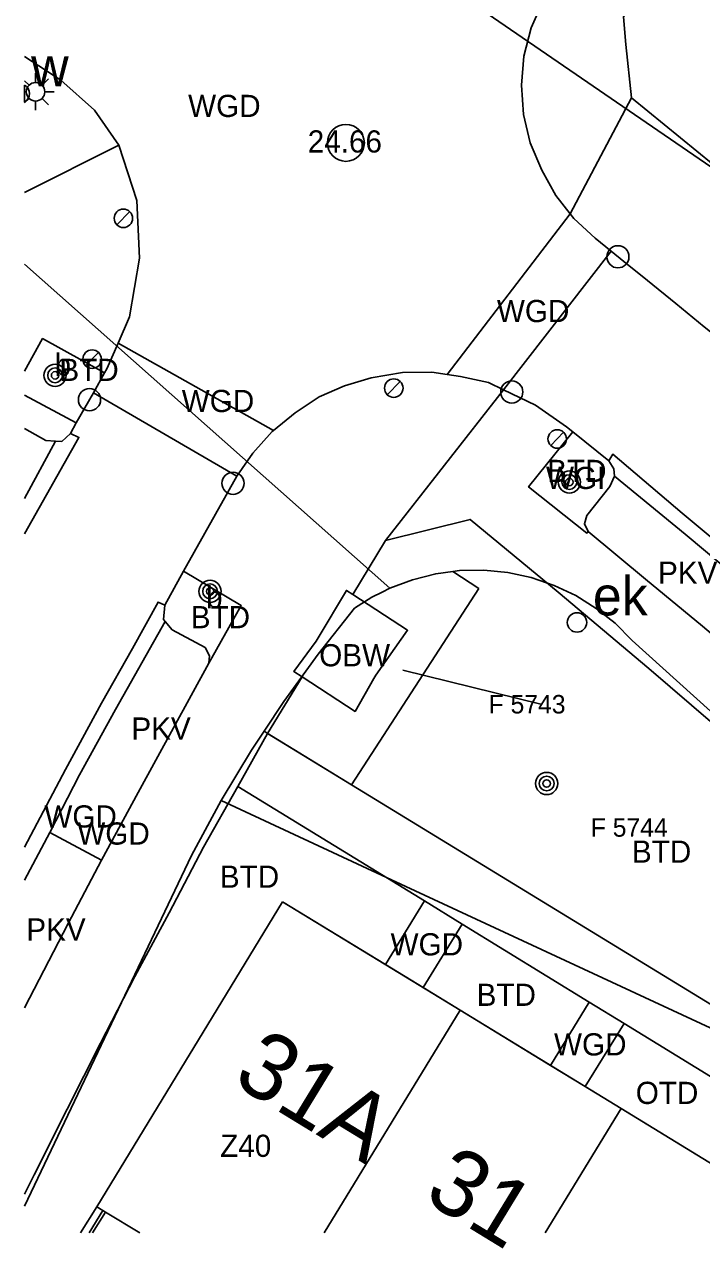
# Model space of a CAD drawing. Extents: x 198240 to 198429, y 356553 to 356721.
# Drawn here: x 198239.79 to 198258.1, y 356553.28 to 356586.38 of the extents above; entities that cross this region are included whole.
import ezdxf

# ---------------------------------------------------------------- set-up
doc = ezdxf.new("R2010")
doc.units = 0
for name, color, linetype in [('Afsluitpaal', 7, 'Continuous'), ('begroeid terreindeel kenmerkpunt', 7, 'Continuous'), ('bijpijling', 7, 'Continuous'), ('BOOM', 7, 'Continuous'), ('Elektrakast', 7, 'Continuous'), ('Grens beheer openbare ruimte', 7, 'Continuous'), ('Grens beheer openbare ruimte wegbeheer', 7, 'Continuous'), ('grens individueel parkeervak', 7, 'Continuous'), ('Grens maaiveld', 7, 'Continuous'), ('hoofdgebouw', 7, 'Continuous'), ('Hoogtepunt', 7, 'Continuous'), ('huisnummerreeks BGT', 7, 'Continuous'), ('identificerend kenmerkpunt pand', 7, 'Continuous'), ('identificerend kenmerkpunt parkeervak', 7, 'Continuous'), ('Inspectieput_rioolput', 7, 'Continuous'), ('kant verharding', 7, 'Continuous'), ('kolk', 7, 'Continuous'), ('LICHTMAST', 7, 'Continuous'), ('muur breder dan 30cm', 7, 'Continuous'), ('onbegroeid terreindeel kenmerkpunt', 7, 'Continuous'), ('overig bouwwerk kenmerkpunt', 7, 'Continuous'), ('overig opstal', 7, 'Continuous'), ('Perceelnummer', 7, 'Continuous'), ('perceelsgrens_definitief', 7, 'Continuous'), ('scheidingmuur boven maaiveld', 7, 'Continuous'), ('schutting geen IMGeo', 7, 'Continuous'), ('tussenmuur', 7, 'Continuous'), ('vlakafsluiter', 7, 'Continuous'), ('waterleidingput', 7, 'Continuous'), ('wegdeel kenmerkpunt', 7, 'Continuous'), ('weginrichtingselement', 7, 'Continuous'), ('weginrichtingselement lijn', 7, 'Continuous')]:
    doc.layers.add(name, color=color, linetype=linetype)

msp = doc.modelspace()

# ---------------------------------------------------------------- linework, layer by layer
at = {"layer": 'Afsluitpaal'}
for p, q in [((198242.636, 356581.32), (198242.286, 356580.963)), ((198241.791, 356577.511), (198241.441, 356577.154)), ((198249.95, 356576.728), (198249.6, 356576.371)), ((198254.371, 356575.354), (198254.021, 356574.997))]:
    msp.add_line(p, q, dxfattribs=at)
for centre in [(198242.463, 356581.14), (198241.618, 356577.331), (198249.777, 356576.548), (198254.198, 356575.174)]:
    msp.add_circle(centre, 0.25, dxfattribs=at)
at = {"layer": 'bijpijling'}
msp.add_lwpolyline([(198250.02, 356568.921), (198253.758, 356568)], dxfattribs=at)
at = {"layer": 'BOOM'}
for centre, radius in [((198240.615, 356576.894), 0.3), ((198240.615, 356576.894), 0.2), ((198240.615, 356576.894), 0.1), ((198254.526, 356574.008), 0.3), ((198254.526, 356574.008), 0.2), ((198254.526, 356574.008), 0.1), ((198244.808, 356571.052), 0.3), ((198244.808, 356571.052), 0.2), ((198244.808, 356571.052), 0.1), ((198253.913, 356565.857), 0.3), ((198253.913, 356565.857), 0.2), ((198253.913, 356565.857), 0.1)]:
    msp.add_circle(centre, radius, dxfattribs=at)
at = {"layer": 'Elektrakast'}
msp.add_circle((198254.733, 356570.212), 0.263, dxfattribs=at)
msp.add_circle((198254.733, 356570.212), 0.263, dxfattribs=at)
at = {"layer": 'Grens beheer openbare ruimte'}
for p, q in [((198249.557, 356572.425), (198252.744, 356576.504)), ((198245.558, 356565.779), (198246.362, 356567.205))]:
    msp.add_line(p, q, dxfattribs=at)
at = {"layer": 'Grens beheer openbare ruimte wegbeheer'}
msp.add_line((198242.319, 356577.767), (198246.52, 356575.403), dxfattribs=at)
at = {"layer": 'grens individueel parkeervak'}
msp.add_line((198240.471, 356564.536), (198241.874, 356563.779), dxfattribs=at)
at = {"layer": 'Grens maaiveld'}
for p, q in [((198254.551, 356581.262), (198251.221, 356576.917)), ((198252.744, 356576.504), (198255.653, 356580.25)), ((198241.65, 356576.424), (198245.534, 356574.17)), ((198245.558, 356565.779), (198250.608, 356562.68)), ((198246.769, 356562.661), (198249.553, 356560.96)), ((198249.553, 356560.96), (198250.608, 356562.68)), ((198251.627, 356562.055), (198250.608, 356562.68)), ((198250.573, 356560.337), (198251.627, 356562.055)), ((198255.066, 356559.945), (198251.627, 356562.055)), ((198250.573, 356560.337), (198249.553, 356560.96)), ((198250.573, 356560.337), (198251.576, 356559.724)), ((198254.016, 356558.234), (198255.066, 356559.945)), ((198255.066, 356559.945), (198256.006, 356559.368)), ((198251.576, 356559.724), (198254.016, 356558.234)), ((198254.957, 356557.659), (198256.006, 356559.368)), ((198256.006, 356559.368), (198259.345, 356557.319)), ((198254.016, 356558.234), (198254.957, 356557.659)), ((198255.928, 356557.066), (198254.957, 356557.659)), ((198258.3, 356555.616), (198255.928, 356557.066))]:
    msp.add_line(p, q, dxfattribs=at)
for points in [[(198239.787, 356572.605), (198241.259, 356575.215), (198241.033, 356575.321)], [(198255.592, 356574.585), (198255.699, 356574.762), (198257.573, 356573.165), (198259.411, 356571.648), (198260.875, 356570.386), (198262.5, 356568.968), (198264.152, 356567.503), (198265.781, 356566.067), (198267.427, 356564.565), (198269.308, 356562.845), (198271.085, 356561.21), (198272.778, 356559.643), (198274.563, 356557.947), (198276.281, 356556.309), (198277.654, 356554.959), (198278.872, 356553.781), (198278.805, 356553.702)], [(198239.787, 356564.132), (198240.9, 356566.232), (198241.873, 356568.027), (198242.71, 356569.511), (198243.402, 356570.763), (198243.582, 356570.681)]]:
    msp.add_lwpolyline(points, dxfattribs=at)
at = {"layer": 'hoofdgebouw'}
for p, q in [((198241.747, 356554.408), (198241.909, 356554.309)), ((198241.909, 356554.309), (198241.977, 356554.268)), ((198241.977, 356554.268), (198242.907, 356553.702))]:
    msp.add_line(p, q, dxfattribs=at)
at = {"layer": 'Inspectieput_rioolput'}
msp.add_circle((198248.481, 356583.18), 0.5, dxfattribs=at)
at = {"layer": 'kant verharding'}
for p, q in [((198256.055, 356585.841), (198256.204, 356584.398)), ((198256.204, 356584.398), (198258.856, 356582.232)), ((198241.65, 356576.424), (198241.954, 356576.965)), ((198241.19, 356575.606), (198241.65, 356576.424)), ((198241.033, 356575.321), (198241.19, 356575.606)), ((198255.592, 356574.585), (198254.621, 356575.367)), ((198240.624, 356575.114), (198239.787, 356573.563)), ((198244.093, 356571.595), (198245.534, 356574.17)), ((198249.557, 356572.425), (198248.665, 356570.967)), ((198243.582, 356570.681), (198244.093, 356571.595)), ((198247.299, 356568.737), (198246.362, 356567.205)), ((198246.362, 356567.205), (198268.466, 356553.702))]:
    msp.add_line(p, q, dxfattribs=at)
for points in [[(198256.055, 356585.841), (198255.989, 356586.59), (198257.636, 356589.092), (198257.545, 356589.159), (198257.648, 356589.317)], [(198254.653, 356588.377), (198254.218, 356587.696), (198253.817, 356587.017), (198253.496, 356586.295), (198253.293, 356585.524), (198253.233, 356584.742), (198253.288, 356583.945), (198253.466, 356583.177), (198253.779, 356582.443), (198254.159, 356581.761), (198254.551, 356581.262)], [(198239.787, 356585.517), (198240.771, 356584.875), (198241.681, 356584.067), (198242.343, 356583.12)], [(198242.343, 356583.12), (198242.826, 356581.623), (198242.899, 356580.059), (198242.63, 356578.478), (198242.319, 356577.767)], [(198254.551, 356581.262), (198254.647, 356581.139), (198255.223, 356580.6), (198255.653, 356580.25)], [(198255.653, 356580.25), (198255.998, 356579.968), (198256.636, 356579.462), (198257.404, 356578.839), (198258.176, 356578.204), (198258.972, 356577.566), (198259.754, 356576.936), (198260.504, 356576.293), (198261.252, 356575.651), (198262.011, 356574.998)], [(198239.787, 356577.006), (198240.279, 356577.889), (198241.954, 356576.965)], [(198242.319, 356577.767), (198242.015, 356577.073), (198241.954, 356576.965)], [(198251.221, 356576.917), (198250.807, 356576.977), (198250.015, 356576.968), (198249.162, 356576.831), (198248.443, 356576.611), (198247.76, 356576.317), (198247.107, 356575.882), (198246.52, 356575.403)], [(198252.744, 356576.504), (198252.341, 356576.698), (198251.581, 356576.864), (198251.221, 356576.917)], [(198254.621, 356575.367), (198254.449, 356575.506), (198253.614, 356576.084), (198252.744, 356576.504)], [(198241.19, 356575.606), (198239.787, 356576.358)], [(198239.787, 356575.454), (198240.361, 356575.135), (198240.624, 356575.114)], [(198240.624, 356575.114), (198240.796, 356575.101), (198241.033, 356575.321)], [(198246.52, 356575.403), (198246.487, 356575.376), (198245.964, 356574.785), (198245.534, 356574.17)], [(198254.621, 356575.367), (198253.424, 356573.876), (198255.001, 356572.628), (198255.033, 356572.668)], [(198255.749, 356574.163), (198255.73, 356574.365), (198255.592, 356574.585)], [(198255.033, 356572.668), (198254.933, 356572.882), (198254.998, 356573.106), (198255.623, 356573.892), (198255.749, 356574.163)], [(198260.773, 356569.956), (198260.331, 356570.341), (198259.198, 356571.307), (198257.655, 356572.598), (198255.749, 356574.163)], [(198273.472, 356553.702), (198272.817, 356554.33), (198270.586, 356556.469), (198268.355, 356558.558), (198265.988, 356560.735), (198263.879, 356562.635), (198261.324, 356564.926), (198258.988, 356566.982), (198256.674, 356568.965), (198254.222, 356571.03), (198251.842, 356572.999), (198249.557, 356572.425)], [(198259.73, 356568.743), (198259.258, 356569.155), (198258.124, 356570.109), (198256.585, 356571.386), (198255.033, 356572.668)], [(198244.777, 356569.107), (198245.649, 356570.669), (198244.093, 356571.595)], [(198243.582, 356570.681), (198243.547, 356570.29), (198243.591, 356570.239)], [(198240.471, 356564.536), (198241.274, 356566.087), (198242.254, 356567.862), (198243.591, 356570.239)], [(198243.591, 356570.239), (198243.785, 356570.014), (198244.671, 356569.53), (198244.796, 356569.311), (198244.777, 356569.107)], [(198244.777, 356569.107), (198242.867, 356565.617), (198241.874, 356563.779)], [(198245.558, 356565.779), (198244.633, 356564.138), (198243.704, 356562.355), (198242.769, 356560.636), (198241.845, 356558.834), (198240.94, 356557.047), (198240.047, 356555.271), (198239.787, 356554.751)], [(198239.787, 356563.246), (198240.471, 356564.536)], [(198241.874, 356563.779), (198240.973, 356562.067), (198239.787, 356559.786)]]:
    msp.add_lwpolyline(points, dxfattribs=at)
at = {"layer": 'kolk'}
for centre in [(198255.839, 356580.1), (198241.546, 356576.235), (198252.969, 356576.445), (198245.428, 356573.976)]:
    msp.add_circle(centre, 0.3, dxfattribs=at)
at = {"layer": 'LICHTMAST'}
for p, q in [((198240.087, 356584.811), (198240.087, 356585.061)), ((198239.91, 356584.738), (198239.787, 356584.861)), ((198240.264, 356584.738), (198240.441, 356584.915)), ((198239.787, 356584.561), (198239.837, 356584.561)), ((198239.787, 356584.261), (198239.91, 356584.384)), ((198240.441, 356584.207), (198240.264, 356584.384)), ((198240.337, 356584.561), (198240.587, 356584.561)), ((198240.087, 356584.061), (198240.087, 356584.311))]:
    msp.add_line(p, q, dxfattribs=at)
msp.add_circle((198240.087, 356584.561), 0.25, dxfattribs=at)
at = {"layer": 'muur breder dan 30cm'}
for points in [[(198241.747, 356554.408), (198241.306, 356553.702)], [(198241.536, 356553.702), (198241.909, 356554.309)]]:
    msp.add_lwpolyline(points, dxfattribs=at)
at = {"layer": 'overig opstal'}
for points in [[(198247.299, 356568.737), (198247.074, 356568.883), (198247.679, 356569.709), (198247.736, 356569.796), (198248.496, 356571.077), (198248.665, 356570.967)], [(198248.665, 356570.967), (198250.149, 356569.999), (198249.288, 356568.783), (198249.238, 356568.7), (198248.73, 356567.808), (198247.299, 356568.737)]]:
    msp.add_lwpolyline(points, dxfattribs=at)
at = {"layer": 'perceelsgrens_definitief'}
for points in [[(198243.211, 356592.912), (198259.64, 356581.648)], [(198239.787, 356579.903), (198249.672, 356571.138)], [(198251.373, 356571.588), (198250.913, 356571.527), (198250.281, 356571.368), (198249.672, 356571.138)], [(198256.224, 356569.728), (198255.763, 356570.188), (198255.253, 356570.593), (198254.7, 356570.937), (198254.111, 356571.215), (198253.494, 356571.424), (198252.858, 356571.561), (198252.209, 356571.624), (198251.558, 356571.613), (198251.373, 356571.588)], [(198252.074, 356571.131), (198251.373, 356571.588)], [(198248.634, 356565.821), (198252.074, 356571.131)], [(198249.461, 356571.032), (198249.18, 356570.891), (198248.714, 356570.597)], [(198249.672, 356571.138), (198249.461, 356571.032)], [(198248.714, 356570.597), (198247.73, 356569.357), (198246.8, 356568.075), (198246.267, 356567.27)], [(198262.119, 356564.407), (198256.224, 356569.728)], [(198246.267, 356567.27), (198245.925, 356566.755), (198245.108, 356565.399)], [(198246.352, 356567.218), (198246.267, 356567.27)], [(198246.352, 356567.218), (198248.634, 356565.821)], [(198245.108, 356565.399), (198244.302, 356563.91)], [(198245.108, 356565.399), (198250.107, 356563.075)], [(198244.302, 356563.91), (198239.787, 356554.429)], [(198250.107, 356563.075), (198259.986, 356558.483), (198264.044, 356562.661)]]:
    msp.add_lwpolyline(points, dxfattribs=at)
at = {"layer": 'scheidingmuur boven maaiveld'}
for p, q in [((198251.576, 356559.724), (198246.769, 356562.661)), ((198251.576, 356559.724), (198255.928, 356557.066)), ((198260.28, 356554.407), (198255.928, 356557.066))]:
    msp.add_line(p, q, dxfattribs=at)
msp.add_lwpolyline([(198241.747, 356554.408), (198241.745, 356554.409), (198246.769, 356562.661)], dxfattribs=at)
at = {"layer": 'schutting geen IMGeo'}
msp.add_lwpolyline([(198241.977, 356554.268), (198241.63, 356553.702)], dxfattribs=at)
at = {"layer": 'tussenmuur'}
for p, q in [((198251.576, 356559.724), (198247.891, 356553.702)), ((198253.869, 356553.702), (198255.928, 356557.066))]:
    msp.add_line(p, q, dxfattribs=at)
at = {"layer": 'vlakafsluiter'}
for p, q in [((198254.551, 356581.262), (198256.204, 356584.398)), ((198239.787, 356581.841), (198242.343, 356583.12))]:
    msp.add_line(p, q, dxfattribs=at)
at = {"layer": 'waterleidingput'}
msp.add_line((198239.787, 356584.743), (198239.787, 356584.281), dxfattribs=at)
msp.add_line((198239.787, 356584.743), (198239.787, 356584.281), dxfattribs=at)
msp.add_arc((198239.663, 356584.512), 0.263, 298.2918, 61.7082, dxfattribs=at)
msp.add_arc((198239.663, 356584.512), 0.263, 298.2918, 61.7082, dxfattribs=at)
at = {"layer": 'weginrichtingselement lijn'}
for points in [[(198239.787, 356572.605), (198241.259, 356575.215), (198241.033, 356575.321)], [(198239.787, 356564.132), (198240.9, 356566.232), (198241.873, 356568.027), (198242.71, 356569.511), (198243.402, 356570.763), (198243.582, 356570.681)]]:
    msp.add_lwpolyline(points, dxfattribs=at)

# ---------------------------------------------------------------- texts
at = {"layer": 'begroeid terreindeel kenmerkpunt'}
for p in [(198240.732, 356576.743), (198253.927, 356574.01), (198244.285, 356570.055), (198256.219, 356563.715), (198245.072, 356563.037), (198252.018, 356559.843)]:
    msp.add_text('BTD', height=0.6, dxfattribs=at).set_placement(p)
at = {"layer": 'Elektrakast'}
msp.add_text('ek', height=1.05, dxfattribs=at).set_placement((198255.162, 356570.403))
at = {"layer": 'Hoogtepunt'}
msp.add_text('24.66', height=0.6, dxfattribs=at).set_placement((198247.449, 356582.919))
msp.add_text('24.66', height=0.6, dxfattribs=at).set_placement((198247.449, 356582.919))
at = {"layer": 'huisnummerreeks BGT'}
for s, p in [('31A', (198245.371, 356557.772)), ('31', (198250.539, 356554.615))]:
    msp.add_text(s, height=1.8, rotation=328.6, dxfattribs=at).set_placement(p)
at = {"layer": 'identificerend kenmerkpunt pand'}
msp.add_text('Z40', height=0.6, dxfattribs=at).set_placement((198245.081, 356555.76))
at = {"layer": 'identificerend kenmerkpunt parkeervak'}
for p in [(198256.925, 356571.257), (198242.679, 356567.042), (198239.837, 356561.609)]:
    msp.add_text('PKV', height=0.6, dxfattribs=at).set_placement(p)
at = {"layer": 'onbegroeid terreindeel kenmerkpunt'}
msp.add_text('OTD', height=0.6, dxfattribs=at).set_placement((198256.322, 356557.191))
at = {"layer": 'overig bouwwerk kenmerkpunt'}
msp.add_text('OBW', height=0.6, dxfattribs=at).set_placement((198247.76, 356569.025))
at = {"layer": 'Perceelnummer'}
for s, p in [('F 5743', (198252.341, 356567.75)), ('F 5744', (198255.105, 356564.418))]:
    msp.add_text(s, height=0.5, dxfattribs=at).set_placement(p)
at = {"layer": 'waterleidingput'}
msp.add_text('w', height=1.05, dxfattribs=at).set_placement((198239.967, 356584.71))
at = {"layer": 'wegdeel kenmerkpunt'}
for p in [(198244.214, 356583.88), (198252.566, 356578.333), (198244.041, 356575.901), (198240.325, 356564.666), (198241.216, 356564.204), (198249.69, 356561.208), (198254.111, 356558.502)]:
    msp.add_text('WGD', height=0.6, dxfattribs=at).set_placement(p)
at = {"layer": 'weginrichtingselement'}
for s, p in [('b', (198240.602, 356576.88)), ('WGI', (198253.894, 356573.82)), ('b', (198244.7, 356570.595))]:
    msp.add_text(s, height=0.6, dxfattribs=at).set_placement(p)

doc.saveas('drawing.dxf')
